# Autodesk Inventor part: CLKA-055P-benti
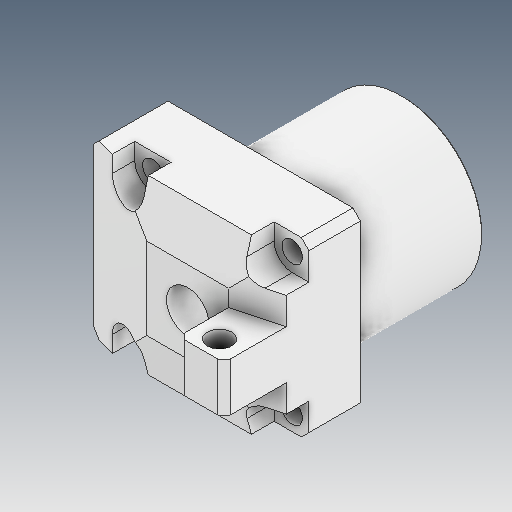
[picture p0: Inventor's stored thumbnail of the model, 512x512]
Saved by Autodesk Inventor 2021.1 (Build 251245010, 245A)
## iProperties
Created: 2021-06
Part Number: CLKA-055P-benti
Material: Ogólny
Document SubType Name: Modeling
Designer: user
Density: 1 g/cm^3
Appearance: Domyślna
Author: user
Revision Number: ÈÎºÎ
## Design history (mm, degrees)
feature "ÇÐ³ý-Ðý×ª5"
node "Bryła1"
